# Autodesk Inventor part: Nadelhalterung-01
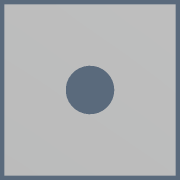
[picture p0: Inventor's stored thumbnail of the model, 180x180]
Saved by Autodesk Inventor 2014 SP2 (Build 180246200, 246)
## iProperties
Created: 2014-04
Part Number: Nadelhalterung-01
Project: Verstellbarer Werkstückanschlag
Material: Aluminium 6061
Document SubType Name: Modeling
Designer: e_dammj
Density: 2.71 g/cm^3
Appearance: Aluminium - flach
Company: VDW-Nachwuchsstiftung
Title: Nadelhalterung
Author: e_dammj
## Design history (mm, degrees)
derived "Nadelhalterung.ipt"
feature "Volumenkörper1::Nadelhalterung.ipt"
tag "Bezeichnung1"
node "Volumenkörper1"
other parameters: "d2" = 11.5, "d3" = 0, "d4" = 15, "d5" = 1.5, "d6" = 0, "d7" = 8.5, "d9" = 15, "d10" = 3.5, "d15" = 3, "d17" = 1, "d18" = 3, "d19" = 45 deg, "d21" = 0, "d23" = 0, "d24" = 11.599
